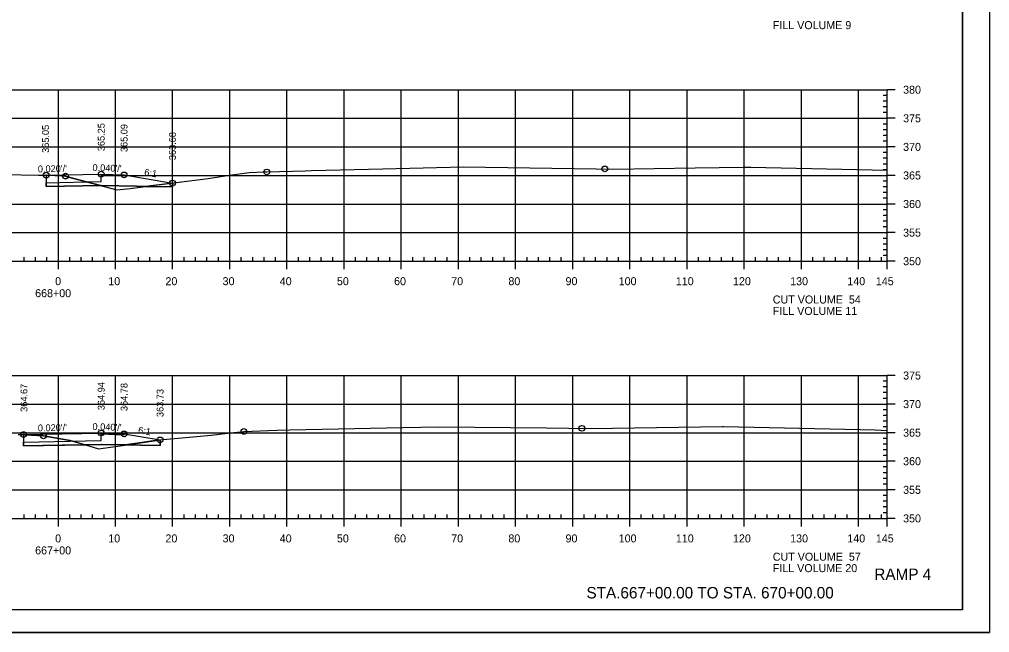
# Model space of a CAD drawing. Extents: x 1359801 to 1362404, y 372415 to 374228.
# Drawn here: x 1361813.1 to 1361982.8, y 373801.3 to 373908.6 of the extents above; entities that cross this region are included whole.
import ezdxf

# ---------------------------------------------------------------- set-up
doc = ezdxf.new("R2010")
doc.units = 0
for name, color, linetype in [('S_DRG_PT_SYM', 7, 'Continuous'), ('S_ELECTRIC_UTILITIES_ANNOT', 7, 'Continuous'), ('S_IRON_PIN', 7, 'Continuous'), ('S_MAILBOX', 7, 'Continuous'), ('S_PRIMARY_CTL', 7, 'Continuous'), ('S_SANITARY_SEWER', 7, 'Continuous'), ('S_SHOULDER', 7, 'Continuous'), ('S_SIGN', 7, 'Continuous'), ('S_UNDERGROUND_CABLE', 7, 'Continuous'), ('S_UTL_PT_SYM', 7, 'Continuous'), ('S_WATER_UTILITIES', 7, 'Continuous')]:
    doc.layers.add(name, color=color, linetype=linetype)

msp = doc.modelspace()

# ---------------------------------------------------------------- linework, layer by layer
at = {"layer": 'S_DRG_PT_SYM'}
for points in [[(1361807.48, 373881.51), (1361816.43, 373881.35), (1361817.75, 373881.33), (1361820.73, 373881.18), (1361821.14, 373881.16), (1361822.15, 373880.87), (1361830.12, 373878.75), (1361832.43, 373879), (1361836.36, 373879.53), (1361846.08, 373880.71), (1361849.83, 373881.3), (1361853.29, 373881.81), (1361855.88, 373881.88), (1361856.35, 373881.88), (1361863.07, 373882.1), (1361864.21, 373882.14), (1361876.65, 373882.44), (1361890.77, 373882.8), (1361914.01, 373882.44), (1361916.96, 373882.39), (1361931.29, 373882.6), (1361939.68, 373882.72), (1361940.12, 373882.73), (1361941.06, 373882.71), (1361964.89, 373882.2)], [(1361812.84, 373835.96), (1361813.79, 373835.94), (1361814.12, 373835.92), (1361817.29, 373835.71), (1361818.91, 373835.44), (1361821.93, 373834.91), (1361825.25, 373833.95), (1361826.93, 373833.46), (1361831.12, 373834.05), (1361838.25, 373835.08), (1361841.51, 373835.35), (1361846.62, 373835.84), (1361850, 373836.23), (1361852.35, 373836.48), (1361858.11, 373836.7), (1361860.38, 373836.77), (1361880.19, 373837.18), (1361886.48, 373837.31), (1361905.29, 373837.09), (1361913.02, 373837.01), (1361936.09, 373837.35), (1361936.2, 373837.35), (1361936.33, 373837.35), (1361962.79, 373836.75), (1361964.89, 373836.66)]]:
    msp.add_lwpolyline(points, dxfattribs=at)
at = {"layer": 'S_ELECTRIC_UTILITIES_ANNOT'}
for p, q in [((1361827.24, 373879.52), (1361822.15, 373880.87)), ((1361839.85, 373879.95), (1361835.15, 373879.36)), ((1361839.84, 373879.27), (1361839.85, 373879.95)), ((1361827.39, 373879.52), (1361827.24, 373879.52)), ((1361835.15, 373879.36), (1361827.39, 373879.52)), ((1361835.15, 373879.36), (1361839.84, 373879.27)), ((1361813.79, 373835.94), (1361813.79, 373833.94)), ((1361813.79, 373833.94), (1361824.53, 373834.15)), ((1361824.53, 373834.15), (1361821.93, 373834.91)), ((1361827.39, 373834.21), (1361824.53, 373834.15)), ((1361837.69, 373835), (1361831.63, 373834.13)), ((1361831.63, 373834.13), (1361837.69, 373834.01)), ((1361837.69, 373834.01), (1361837.69, 373835))]:
    msp.add_line(p, q, dxfattribs=at)
for points in [[(1361822.15, 373880.87), (1361821.14, 373881.16), (1361820.73, 373881.18), (1361817.75, 373881.33)], [(1361817.75, 373881.33), (1361817.75, 373879.33), (1361827.24, 373879.52)], [(1361827.24, 373879.52), (1361830.12, 373878.75), (1361832.43, 373879), (1361835.15, 373879.36), (1361835.15, 373879.36)], [(1361821.93, 373834.91), (1361818.91, 373835.44), (1361817.29, 373835.71), (1361814.12, 373835.92), (1361813.79, 373835.94)], [(1361824.53, 373834.15), (1361825.25, 373833.95), (1361826.93, 373833.46), (1361831.12, 373834.05), (1361831.63, 373834.13)], [(1361831.63, 373834.13), (1361827.42, 373834.21), (1361827.39, 373834.21)]]:
    msp.add_lwpolyline(points, dxfattribs=at)
at = {"layer": 'S_MAILBOX'}
for p, q in [((1361674.89, 373896.27), (1361964.89, 373896.27)), ((1361819.89, 373866.27), (1361819.89, 373896.27)), ((1361829.89, 373866.27), (1361829.89, 373896.27)), ((1361839.89, 373866.27), (1361839.89, 373896.27)), ((1361849.89, 373866.27), (1361849.89, 373896.27)), ((1361859.89, 373866.27), (1361859.89, 373896.27)), ((1361869.89, 373866.27), (1361869.89, 373896.27)), ((1361879.89, 373866.27), (1361879.89, 373896.27)), ((1361889.89, 373866.27), (1361889.89, 373896.27)), ((1361899.89, 373866.27), (1361899.89, 373896.27)), ((1361909.89, 373866.27), (1361909.89, 373896.27)), ((1361919.89, 373866.27), (1361919.89, 373896.27)), ((1361929.89, 373866.27), (1361929.89, 373896.27)), ((1361939.89, 373866.27), (1361939.89, 373896.27)), ((1361949.89, 373866.27), (1361949.89, 373896.27)), ((1361959.89, 373866.27), (1361959.89, 373896.27)), ((1361964.89, 373866.27), (1361964.89, 373896.27)), ((1361674.89, 373891.27), (1361964.89, 373891.27)), ((1361674.89, 373886.27), (1361964.89, 373886.27)), ((1361827.39, 373881.27), (1361964.89, 373881.27)), ((1361674.89, 373876.27), (1361964.89, 373876.27)), ((1361674.89, 373871.27), (1361964.89, 373871.27)), ((1361674.89, 373866.27), (1361964.89, 373866.27)), ((1361674.89, 373846.27), (1361964.89, 373846.27)), ((1361819.89, 373821.27), (1361819.89, 373846.27)), ((1361829.89, 373821.27), (1361829.89, 373846.27)), ((1361839.89, 373821.27), (1361839.89, 373846.27)), ((1361849.89, 373821.27), (1361849.89, 373846.27)), ((1361859.89, 373821.27), (1361859.89, 373846.27)), ((1361869.89, 373821.27), (1361869.89, 373846.27)), ((1361879.89, 373821.27), (1361879.89, 373846.27)), ((1361889.89, 373821.27), (1361889.89, 373846.27)), ((1361899.89, 373821.27), (1361899.89, 373846.27)), ((1361909.89, 373821.27), (1361909.89, 373846.27)), ((1361919.89, 373821.27), (1361919.89, 373846.27)), ((1361929.89, 373821.27), (1361929.89, 373846.27)), ((1361939.89, 373821.27), (1361939.89, 373846.27)), ((1361949.89, 373821.27), (1361949.89, 373846.27)), ((1361959.89, 373821.27), (1361959.89, 373846.27)), ((1361964.89, 373821.27), (1361964.89, 373846.27)), ((1361674.89, 373841.27), (1361964.89, 373841.27)), ((1361674.89, 373836.27), (1361964.89, 373836.27)), ((1361674.89, 373831.27), (1361964.89, 373831.27)), ((1361674.89, 373826.27), (1361964.89, 373826.27)), ((1361674.89, 373821.27), (1361964.89, 373821.27))]:
    msp.add_line(p, q, dxfattribs=at)
at = {"layer": 'S_SANITARY_SEWER'}
for points in [[(1361817.75, 373881.33), (1361827.39, 373881.52), (1361831.39, 373881.36), (1361839.85, 373879.95)], [(1361813.79, 373835.94), (1361827.39, 373836.21), (1361831.39, 373836.05), (1361837.69, 373835)]]:
    msp.add_lwpolyline(points, dxfattribs=at)
at = {"layer": 'S_SHOULDER'}
for p, q in [((1361839.85, 373879.95), (1361839.85, 373879.95)), ((1361839.85, 373879.95), (1361839.85, 373879.27)), ((1361839.85, 373879.27), (1361839.84, 373879.27)), ((1361839.85, 373879.28), (1361839.85, 373879.28)), ((1361813.79, 373833.94), (1361813.79, 373834.61)), ((1361649.49, 373801.3), (1361982.82, 373801.3))]:
    msp.add_line(p, q, dxfattribs=at)
for points in [[(1361649.48, 374014.63), (1361982.82, 374014.63), (1361982.82, 373801.29), (1361649.48, 373801.29)], [(1361895.81, 374010.73), (1361895.81, 374000.85), (1361931.54, 374000.85), (1361931.54, 373997.93), (1361954.74, 373997.93), (1361954.74, 373973.6), (1361978.07, 373973.6), (1361978.07, 373805.27), (1361661.89, 373805.27), (1361661.89, 374010.73)]]:
    msp.add_lwpolyline(points, close=True, dxfattribs=at)
for points in [[(1361817.75, 373879.99), (1361827.39, 373880.19), (1361827.39, 373881.35)], [(1361827.39, 373881.35), (1361831.37, 373881.19), (1361831.39, 373881.36), (1361839.85, 373879.95)], [(1361839.84, 373879.27), (1361827.39, 373879.52), (1361817.75, 373879.33), (1361817.75, 373879.99)], [(1361813.79, 373834.61), (1361827.39, 373834.88), (1361827.39, 373836.04)], [(1361827.39, 373836.04), (1361831.37, 373835.88), (1361831.39, 373836.05), (1361837.69, 373835)], [(1361837.69, 373835), (1361837.69, 373834.01), (1361827.39, 373834.21), (1361813.79, 373833.94)]]:
    msp.add_lwpolyline(points, dxfattribs=at)
for centre in [(1361817.75, 373881.33), (1361821.14, 373881.16), (1361827.39, 373881.52), (1361831.39, 373881.36), (1361856.35, 373881.88), (1361915.5, 373882.42), (1361839.85, 373879.95), (1361911.5, 373837.03), (1361813.79, 373835.94), (1361817.29, 373835.71), (1361827.39, 373836.21), (1361831.39, 373836.05), (1361837.69, 373835), (1361852.35, 373836.48)]:
    msp.add_circle(centre, 0.5, dxfattribs=at)
at = {"layer": 'S_UNDERGROUND_CABLE'}
for p, q in [((1361839.85, 373879.95), (1361839.85, 373879.95)), ((1361839.85, 373879.95), (1361839.85, 373879.27)), ((1361813.79, 373835.94), (1361813.79, 373833.94))]:
    msp.add_line(p, q, dxfattribs=at)
for points in [[(1361817.75, 373881.33), (1361817.75, 373879.33), (1361827.39, 373879.52), (1361839.84, 373879.27)], [(1361813.79, 373833.94), (1361827.39, 373834.21), (1361837.69, 373834.01), (1361837.69, 373835)]]:
    msp.add_lwpolyline(points, dxfattribs=at)
at = {"layer": 'S_UTL_PT_SYM'}
for q in [(1361978.07, 374010.73), (1361661.89, 373805.27)]:
    msp.add_line((1361978.07, 373805.27), q, dxfattribs=at)
at = {"layer": 'S_WATER_UTILITIES'}
for p, q in [((1361964.89, 373895.27), (1361964.19, 373895.27)), ((1361964.89, 373866.27), (1361964.89, 373896.27)), ((1361966.29, 373896.27), (1361964.89, 373896.27)), ((1361964.89, 373894.27), (1361964.19, 373894.27)), ((1361964.89, 373893.27), (1361964.19, 373893.27)), ((1361964.89, 373892.27), (1361964.19, 373892.27)), ((1361964.89, 373890.27), (1361964.19, 373890.27)), ((1361966.29, 373891.27), (1361964.89, 373891.27)), ((1361964.89, 373889.27), (1361964.19, 373889.27)), ((1361964.89, 373888.27), (1361964.19, 373888.27)), ((1361964.89, 373887.27), (1361964.19, 373887.27)), ((1361964.89, 373885.27), (1361964.19, 373885.27)), ((1361966.29, 373886.27), (1361964.89, 373886.27)), ((1361964.89, 373884.27), (1361964.19, 373884.27)), ((1361964.89, 373883.27), (1361964.19, 373883.27)), ((1361964.89, 373882.27), (1361964.19, 373882.27)), ((1361964.89, 373880.27), (1361964.19, 373880.27)), ((1361966.29, 373881.27), (1361964.89, 373881.27)), ((1361964.89, 373879.27), (1361964.19, 373879.27)), ((1361964.89, 373878.27), (1361964.19, 373878.27)), ((1361964.89, 373877.27), (1361964.19, 373877.27)), ((1361966.29, 373876.27), (1361964.89, 373876.27)), ((1361964.89, 373875.27), (1361964.19, 373875.27)), ((1361964.89, 373874.27), (1361964.19, 373874.27)), ((1361964.89, 373873.27), (1361964.19, 373873.27)), ((1361964.89, 373872.27), (1361964.19, 373872.27)), ((1361966.29, 373871.27), (1361964.89, 373871.27)), ((1361964.89, 373870.27), (1361964.19, 373870.27)), ((1361964.89, 373869.27), (1361964.19, 373869.27)), ((1361964.89, 373868.27), (1361964.19, 373868.27)), ((1361674.89, 373866.27), (1361964.89, 373866.27)), ((1361813.89, 373866.27), (1361813.89, 373866.97)), ((1361815.89, 373866.27), (1361815.89, 373866.97)), ((1361817.89, 373866.27), (1361817.89, 373866.97)), ((1361819.89, 373864.87), (1361819.89, 373866.27)), ((1361821.89, 373866.27), (1361821.89, 373866.97)), ((1361823.89, 373866.27), (1361823.89, 373866.97)), ((1361825.89, 373866.27), (1361825.89, 373866.97)), ((1361827.89, 373866.27), (1361827.89, 373866.97)), ((1361829.89, 373864.87), (1361829.89, 373866.27)), ((1361831.89, 373866.27), (1361831.89, 373866.97)), ((1361833.89, 373866.27), (1361833.89, 373866.97)), ((1361835.89, 373866.27), (1361835.89, 373866.97)), ((1361837.89, 373866.27), (1361837.89, 373866.97)), ((1361839.89, 373864.87), (1361839.89, 373866.27)), ((1361841.89, 373866.27), (1361841.89, 373866.97)), ((1361843.89, 373866.27), (1361843.89, 373866.97)), ((1361845.89, 373866.27), (1361845.89, 373866.97)), ((1361847.89, 373866.27), (1361847.89, 373866.97)), ((1361849.89, 373864.87), (1361849.89, 373866.27)), ((1361851.89, 373866.27), (1361851.89, 373866.97)), ((1361853.89, 373866.27), (1361853.89, 373866.97)), ((1361855.89, 373866.27), (1361855.89, 373866.97)), ((1361857.89, 373866.27), (1361857.89, 373866.97)), ((1361859.89, 373864.87), (1361859.89, 373866.27)), ((1361861.89, 373866.27), (1361861.89, 373866.97)), ((1361863.89, 373866.27), (1361863.89, 373866.97)), ((1361865.89, 373866.27), (1361865.89, 373866.97)), ((1361867.89, 373866.27), (1361867.89, 373866.97)), ((1361869.89, 373864.87), (1361869.89, 373866.27)), ((1361871.89, 373866.27), (1361871.89, 373866.97)), ((1361873.89, 373866.27), (1361873.89, 373866.97)), ((1361875.89, 373866.27), (1361875.89, 373866.97)), ((1361877.89, 373866.27), (1361877.89, 373866.97)), ((1361879.89, 373864.87), (1361879.89, 373866.27)), ((1361881.89, 373866.27), (1361881.89, 373866.97)), ((1361883.89, 373866.27), (1361883.89, 373866.97)), ((1361885.89, 373866.27), (1361885.89, 373866.97)), ((1361887.89, 373866.27), (1361887.89, 373866.97)), ((1361889.89, 373864.87), (1361889.89, 373866.27)), ((1361891.89, 373866.27), (1361891.89, 373866.97)), ((1361893.89, 373866.27), (1361893.89, 373866.97)), ((1361895.89, 373866.27), (1361895.89, 373866.97)), ((1361897.89, 373866.27), (1361897.89, 373866.97)), ((1361899.89, 373864.87), (1361899.89, 373866.27)), ((1361901.89, 373866.27), (1361901.89, 373866.97)), ((1361903.89, 373866.27), (1361903.89, 373866.97)), ((1361905.89, 373866.27), (1361905.89, 373866.97)), ((1361907.89, 373866.27), (1361907.89, 373866.97)), ((1361909.89, 373864.87), (1361909.89, 373866.27)), ((1361911.89, 373866.27), (1361911.89, 373866.97)), ((1361913.89, 373866.27), (1361913.89, 373866.97)), ((1361915.89, 373866.27), (1361915.89, 373866.97)), ((1361917.89, 373866.27), (1361917.89, 373866.97)), ((1361919.89, 373864.87), (1361919.89, 373866.27)), ((1361921.89, 373866.27), (1361921.89, 373866.97)), ((1361923.89, 373866.27), (1361923.89, 373866.97)), ((1361925.89, 373866.27), (1361925.89, 373866.97)), ((1361927.89, 373866.27), (1361927.89, 373866.97)), ((1361929.89, 373864.87), (1361929.89, 373866.27)), ((1361931.89, 373866.27), (1361931.89, 373866.97)), ((1361933.89, 373866.27), (1361933.89, 373866.97)), ((1361935.89, 373866.27), (1361935.89, 373866.97)), ((1361937.89, 373866.27), (1361937.89, 373866.97)), ((1361939.89, 373864.87), (1361939.89, 373866.27)), ((1361941.89, 373866.27), (1361941.89, 373866.97)), ((1361943.89, 373866.27), (1361943.89, 373866.97)), ((1361945.89, 373866.27), (1361945.89, 373866.97)), ((1361947.89, 373866.27), (1361947.89, 373866.97)), ((1361949.89, 373864.87), (1361949.89, 373866.27)), ((1361951.89, 373866.27), (1361951.89, 373866.97)), ((1361953.89, 373866.27), (1361953.89, 373866.97)), ((1361955.89, 373866.27), (1361955.89, 373866.97)), ((1361957.89, 373866.27), (1361957.89, 373866.97)), ((1361959.89, 373864.87), (1361959.89, 373866.27)), ((1361961.89, 373866.27), (1361961.89, 373866.97)), ((1361963.89, 373866.27), (1361963.89, 373866.97)), ((1361964.89, 373867.27), (1361964.19, 373867.27)), ((1361964.89, 373864.87), (1361964.89, 373866.27)), ((1361966.29, 373866.27), (1361964.89, 373866.27)), ((1361964.89, 373821.27), (1361964.89, 373846.27)), ((1361966.29, 373846.27), (1361964.89, 373846.27)), ((1361964.89, 373845.27), (1361964.19, 373845.27)), ((1361964.89, 373844.27), (1361964.19, 373844.27)), ((1361964.89, 373843.27), (1361964.19, 373843.27)), ((1361964.89, 373842.27), (1361964.19, 373842.27)), ((1361966.29, 373841.27), (1361964.89, 373841.27)), ((1361964.89, 373840.27), (1361964.19, 373840.27)), ((1361964.89, 373839.27), (1361964.19, 373839.27)), ((1361964.89, 373838.27), (1361964.19, 373838.27)), ((1361964.89, 373837.27), (1361964.19, 373837.27)), ((1361966.29, 373836.27), (1361964.89, 373836.27)), ((1361964.89, 373835.27), (1361964.19, 373835.27)), ((1361964.89, 373834.27), (1361964.19, 373834.27)), ((1361964.89, 373833.27), (1361964.19, 373833.27)), ((1361964.89, 373832.27), (1361964.19, 373832.27)), ((1361966.29, 373831.27), (1361964.89, 373831.27)), ((1361964.89, 373830.27), (1361964.19, 373830.27)), ((1361964.89, 373829.27), (1361964.19, 373829.27)), ((1361964.89, 373828.27), (1361964.19, 373828.27)), ((1361964.89, 373827.27), (1361964.19, 373827.27)), ((1361966.29, 373826.27), (1361964.89, 373826.27)), ((1361964.89, 373825.27), (1361964.19, 373825.27)), ((1361964.89, 373824.27), (1361964.19, 373824.27)), ((1361813.89, 373821.27), (1361813.89, 373821.97)), ((1361815.89, 373821.27), (1361815.89, 373821.97)), ((1361817.89, 373821.27), (1361817.89, 373821.97)), ((1361821.89, 373821.27), (1361821.89, 373821.97)), ((1361823.89, 373821.27), (1361823.89, 373821.97)), ((1361825.89, 373821.27), (1361825.89, 373821.97)), ((1361827.89, 373821.27), (1361827.89, 373821.97)), ((1361831.89, 373821.27), (1361831.89, 373821.97)), ((1361833.89, 373821.27), (1361833.89, 373821.97)), ((1361835.89, 373821.27), (1361835.89, 373821.97)), ((1361837.89, 373821.27), (1361837.89, 373821.97)), ((1361841.89, 373821.27), (1361841.89, 373821.97)), ((1361843.89, 373821.27), (1361843.89, 373821.97)), ((1361845.89, 373821.27), (1361845.89, 373821.97)), ((1361847.89, 373821.27), (1361847.89, 373821.97)), ((1361851.89, 373821.27), (1361851.89, 373821.97)), ((1361853.89, 373821.27), (1361853.89, 373821.97)), ((1361855.89, 373821.27), (1361855.89, 373821.97)), ((1361857.89, 373821.27), (1361857.89, 373821.97)), ((1361861.89, 373821.27), (1361861.89, 373821.97)), ((1361863.89, 373821.27), (1361863.89, 373821.97)), ((1361865.89, 373821.27), (1361865.89, 373821.97)), ((1361867.89, 373821.27), (1361867.89, 373821.97)), ((1361871.89, 373821.27), (1361871.89, 373821.97)), ((1361873.89, 373821.27), (1361873.89, 373821.97)), ((1361875.89, 373821.27), (1361875.89, 373821.97)), ((1361877.89, 373821.27), (1361877.89, 373821.97)), ((1361881.89, 373821.27), (1361881.89, 373821.97)), ((1361883.89, 373821.27), (1361883.89, 373821.97)), ((1361885.89, 373821.27), (1361885.89, 373821.97)), ((1361887.89, 373821.27), (1361887.89, 373821.97)), ((1361891.89, 373821.27), (1361891.89, 373821.97)), ((1361893.89, 373821.27), (1361893.89, 373821.97)), ((1361895.89, 373821.27), (1361895.89, 373821.97)), ((1361897.89, 373821.27), (1361897.89, 373821.97)), ((1361901.89, 373821.27), (1361901.89, 373821.97)), ((1361903.89, 373821.27), (1361903.89, 373821.97)), ((1361905.89, 373821.27), (1361905.89, 373821.97)), ((1361907.89, 373821.27), (1361907.89, 373821.97)), ((1361911.89, 373821.27), (1361911.89, 373821.97)), ((1361913.89, 373821.27), (1361913.89, 373821.97)), ((1361915.89, 373821.27), (1361915.89, 373821.97)), ((1361917.89, 373821.27), (1361917.89, 373821.97)), ((1361921.89, 373821.27), (1361921.89, 373821.97)), ((1361923.89, 373821.27), (1361923.89, 373821.97)), ((1361925.89, 373821.27), (1361925.89, 373821.97)), ((1361927.89, 373821.27), (1361927.89, 373821.97)), ((1361931.89, 373821.27), (1361931.89, 373821.97)), ((1361933.89, 373821.27), (1361933.89, 373821.97)), ((1361935.89, 373821.27), (1361935.89, 373821.97)), ((1361937.89, 373821.27), (1361937.89, 373821.97)), ((1361941.89, 373821.27), (1361941.89, 373821.97)), ((1361943.89, 373821.27), (1361943.89, 373821.97)), ((1361945.89, 373821.27), (1361945.89, 373821.97)), ((1361947.89, 373821.27), (1361947.89, 373821.97)), ((1361951.89, 373821.27), (1361951.89, 373821.97)), ((1361953.89, 373821.27), (1361953.89, 373821.97)), ((1361955.89, 373821.27), (1361955.89, 373821.97)), ((1361957.89, 373821.27), (1361957.89, 373821.97)), ((1361961.89, 373821.27), (1361961.89, 373821.97)), ((1361963.89, 373821.27), (1361963.89, 373821.97)), ((1361964.89, 373823.27), (1361964.19, 373823.27)), ((1361964.89, 373822.27), (1361964.19, 373822.27)), ((1361674.89, 373821.27), (1361964.89, 373821.27)), ((1361819.89, 373819.87), (1361819.89, 373821.27)), ((1361829.89, 373819.87), (1361829.89, 373821.27)), ((1361839.89, 373819.87), (1361839.89, 373821.27)), ((1361849.89, 373819.87), (1361849.89, 373821.27)), ((1361859.89, 373819.87), (1361859.89, 373821.27)), ((1361869.89, 373819.87), (1361869.89, 373821.27)), ((1361879.89, 373819.87), (1361879.89, 373821.27)), ((1361889.89, 373819.87), (1361889.89, 373821.27)), ((1361899.89, 373819.87), (1361899.89, 373821.27)), ((1361909.89, 373819.87), (1361909.89, 373821.27)), ((1361919.89, 373819.87), (1361919.89, 373821.27)), ((1361929.89, 373819.87), (1361929.89, 373821.27)), ((1361939.89, 373819.87), (1361939.89, 373821.27)), ((1361949.89, 373819.87), (1361949.89, 373821.27)), ((1361959.89, 373819.87), (1361959.89, 373821.27)), ((1361964.89, 373819.87), (1361964.89, 373821.27)), ((1361966.29, 373821.27), (1361964.89, 373821.27))]:
    msp.add_line(p, q, dxfattribs=at)

# ---------------------------------------------------------------- texts
at = {"layer": 'S_IRON_PIN'}
for s, rotation, p in [('365.05', 90, (1361818.25, 373885.22)), ('365.25', 90, (1361827.99, 373885.52)), ('365.09', 90, (1361831.99, 373885.36)), ('363.68', 90, (1361840.45, 373883.95)), ("0.020'/'", 1.1458, (1361816.32, 373881.8)), ("0.040'/'", 357.7094, (1361825.85, 373882.08)), ('6:1', 350.5377, (1361834.85, 373881.29)), ('364.67', 90, (1361814.48, 373839.91)), ('364.94', 90, (1361827.99, 373840.21)), ('364.78', 90, (1361831.99, 373840.05)), ('363.73', 90, (1361838.29, 373839)), ("0.020'/'", 1.1458, (1361816.32, 373836.49)), ("0.040'/'", 357.7094, (1361825.85, 373836.77)), ('6:1', 350.5377, (1361833.77, 373836.16))]:
    msp.add_text(s, height=1.2, rotation=rotation, dxfattribs=at).set_placement(p)
at = {"layer": 'S_PRIMARY_CTL'}
for s, p in [('FILL VOLUME 9', (1361944.89, 373906.87)), ('380', (1361967.69, 373895.57)), ('375', (1361967.69, 373890.57)), ('370', (1361967.69, 373885.57)), ('365', (1361967.69, 373880.57)), ('360', (1361967.69, 373875.57)), ('355', (1361967.69, 373870.57)), ('350', (1361967.69, 373865.57)), ('0', (1361819.33, 373862.07)), ('10', (1361828.63, 373862.07)), ('20', (1361838.63, 373862.07)), ('30', (1361848.63, 373862.07)), ('40', (1361858.63, 373862.07)), ('50', (1361868.63, 373862.07)), ('60', (1361878.63, 373862.07)), ('70', (1361888.63, 373862.07)), ('80', (1361898.63, 373862.07)), ('90', (1361908.63, 373862.07)), ('100', (1361917.93, 373862.07)), ('110', (1361927.93, 373862.07)), ('120', (1361937.93, 373862.07)), ('130', (1361947.93, 373862.07)), ('140', (1361957.93, 373862.07)), ('145', (1361962.92, 373862.07)), ('668+00', (1361815.83, 373859.97)), ('CUT VOLUME  54', (1361944.89, 373858.87)), ('FILL VOLUME 11', (1361944.89, 373856.87)), ('375', (1361967.69, 373845.57)), ('370', (1361967.69, 373840.57)), ('365', (1361967.69, 373835.57)), ('360', (1361967.69, 373830.57)), ('355', (1361967.69, 373825.57)), ('350', (1361967.69, 373820.57)), ('0', (1361819.33, 373817.07)), ('10', (1361828.63, 373817.07)), ('20', (1361838.63, 373817.07)), ('30', (1361848.63, 373817.07)), ('40', (1361858.63, 373817.07)), ('50', (1361868.63, 373817.07)), ('60', (1361878.63, 373817.07)), ('70', (1361888.63, 373817.07)), ('80', (1361898.63, 373817.07)), ('90', (1361908.63, 373817.07)), ('100', (1361917.93, 373817.07)), ('110', (1361927.93, 373817.07)), ('120', (1361937.93, 373817.07)), ('130', (1361947.93, 373817.07)), ('140', (1361957.93, 373817.07)), ('145', (1361962.92, 373817.07)), ('667+00', (1361815.83, 373814.97)), ('CUT VOLUME  57', (1361944.89, 373813.87)), ('FILL VOLUME 20', (1361944.89, 373811.87))]:
    msp.add_text(s, height=1.4, dxfattribs=at).set_placement(p)
at = {"layer": 'S_SHOULDER'}
for p in [(1361864.16, 373882.09), (1361860.33, 373836.72), (1361962.75, 373836.7)]:
    msp.add_text('+', height=0.1, dxfattribs=at).set_placement(p)
at = {"layer": 'S_SIGN'}
for s, p in [('RAMP 4', (1361962.66, 373810.5)), ('STA.667+00.00 TO STA. 670+00.00', (1361912.29, 373807.27))]:
    msp.add_text(s, height=2, dxfattribs=at).set_placement(p)

doc.saveas('drawing.dxf')
